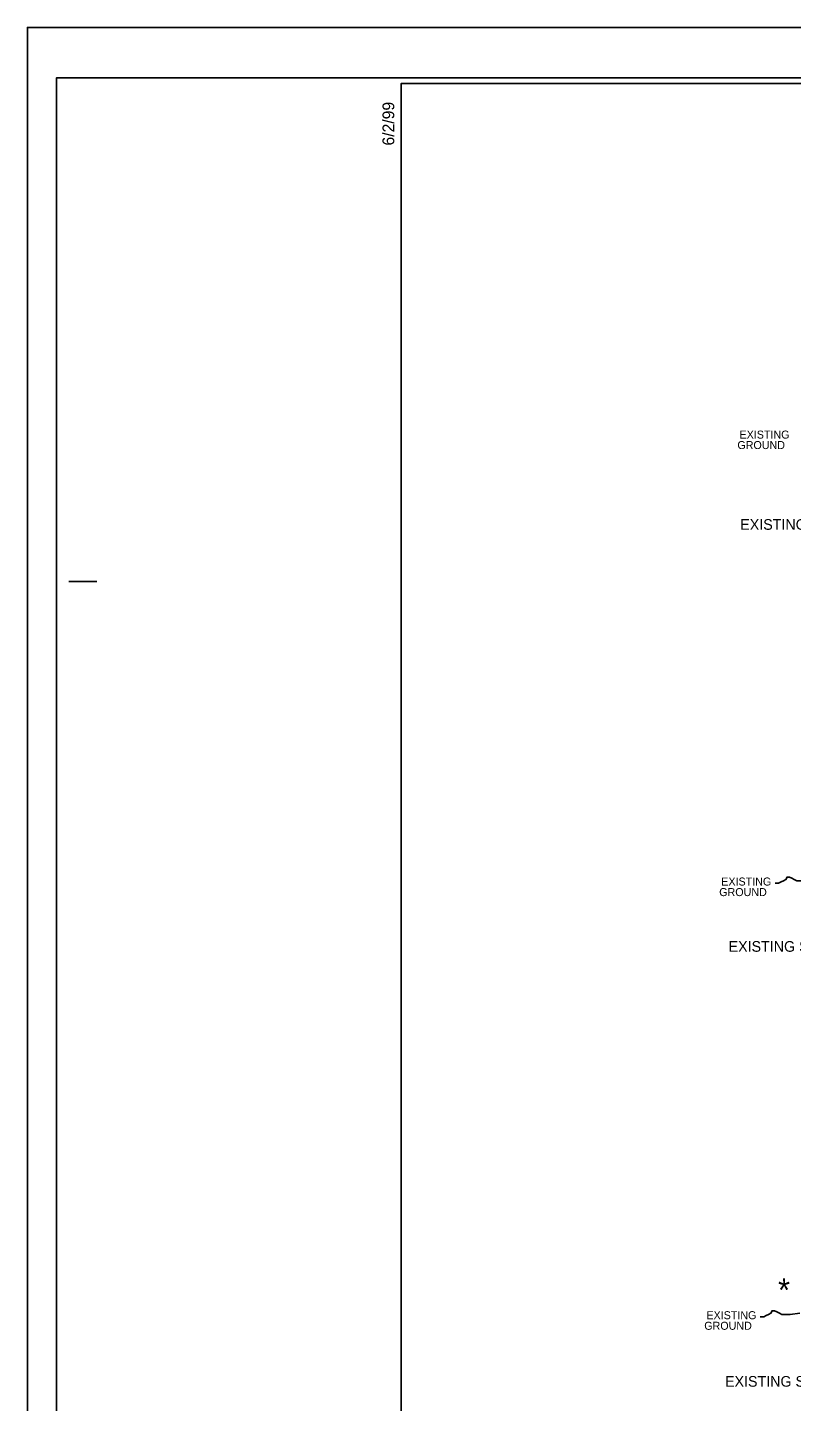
# Model space of a CAD drawing. Extents: x 1022283 to 1026986, y 174822 to 180471.
# Drawn here: x 1022283 to 1023136, y 178936 to 180471 of the extents above; entities that cross this region are included whole.
import ezdxf

# ---------------------------------------------------------------- set-up
doc = ezdxf.new("R2010")
doc.units = 0
for name, color, linetype in [('Sheet Cutting Line CELL', 7, 'Continuous'), ('Sheet Plot Border Inside CELL', 7, 'Continuous'), ('Sheet Plot Border Outside CELL', 7, 'Continuous'), ('Sheet Typical CELL', 7, 'Continuous'), ('Typical Slope Point Local CELL', 7, 'Continuous'), ('Typical Text General CELL', 7, 'Continuous')]:
    doc.layers.add(name, color=color, linetype=linetype)

msp = doc.modelspace()

# ---------------------------------------------------------------- linework, layer by layer
at = {"layer": 'Sheet Cutting Line CELL'}
for p, q in [((1026493.2, 180471.5), (1022283.2, 180471.5)), ((1022283.2, 180471.5), (1022283.2, 177721.5))]:
    msp.add_line(p, q, dxfattribs=at)
at = {"layer": 'Sheet Plot Border Inside CELL'}
msp.add_lwpolyline([(1026482, 180415.4), (1022315.7, 180415.4), (1022315.7, 177777.6), (1026482, 177777.6)], close=True, dxfattribs=at)
at = {"layer": 'Sheet Plot Border Outside CELL'}
msp.add_lwpolyline([(1026493.2, 180471.5), (1022283.2, 180471.5), (1022283.2, 177721.5), (1026493.2, 177721.5)], close=True, dxfattribs=at)
at = {"layer": 'Sheet Typical CELL'}
msp.add_line((1022329.5, 179852.7), (1022360.7, 179852.7), dxfattribs=at)
msp.add_lwpolyline([(1026450.7, 180409), (1022700.7, 180409), (1022700.7, 177784), (1026450.7, 177784)], close=True, dxfattribs=at)
at = {"layer": 'Typical Slope Point Local CELL'}
for points in [[(1023162.4, 179519.6), (1023151.6, 179518.3), (1023149, 179518.3), (1023144.9, 179518.3), (1023142.2, 179518.3), (1023139.5, 179519.6), (1023136.8, 179521), (1023134.1, 179522.3), (1023131.4, 179522.3), (1023130.1, 179519.6), (1023127.4, 179518.3), (1023124.7, 179516.9), (1023122, 179515.6), (1023119.3, 179515.6), (1023118.3, 179515.6)], [(1023162.4, 179519.6), (1023151.6, 179518.3), (1023149, 179518.3), (1023144.9, 179518.3), (1023142.2, 179518.3), (1023139.5, 179519.6), (1023136.8, 179521), (1023134.1, 179522.3), (1023131.4, 179522.3), (1023130.1, 179519.6), (1023127.4, 179518.3), (1023124.7, 179516.9), (1023122, 179515.6), (1023119.3, 179515.6), (1023118.3, 179515.6)], [(1023145.8, 179035.1), (1023135, 179033.8), (1023132.3, 179033.8), (1023128.2, 179033.8), (1023125.6, 179033.8), (1023122.9, 179035.1), (1023120.2, 179036.5), (1023117.5, 179037.8), (1023114.8, 179037.8), (1023113.4, 179035.1), (1023110.7, 179033.8), (1023108, 179032.4), (1023105.4, 179031.1), (1023102.7, 179031.1), (1023101.6, 179031.1)], [(1023145.8, 179035.1), (1023135, 179033.8), (1023132.3, 179033.8), (1023128.2, 179033.8), (1023125.6, 179033.8), (1023122.9, 179035.1), (1023120.2, 179036.5), (1023117.5, 179037.8), (1023114.8, 179037.8), (1023113.4, 179035.1), (1023110.7, 179033.8), (1023108, 179032.4), (1023105.4, 179031.1), (1023102.7, 179031.1), (1023101.6, 179031.1)]]:
    msp.add_lwpolyline(points, dxfattribs=at)

# ---------------------------------------------------------------- texts
at = {"layer": 'Sheet Typical CELL'}
msp.add_text('6/2/99', height=13.12, rotation=90, dxfattribs=at).set_placement((1022692.8, 180339.6))
at = {"layer": 'Typical Slope Point Local CELL'}
for s, height, p in [('EXISTING ', 8.94, (1023078.4, 180012.2)), ('EXISTING ', 8.94, (1023078.4, 180012.2)), ('GROUND', 8.94, (1023076, 180000.5)), ('GROUND', 8.94, (1023076, 180000.5)), ('EXISTING ', 8.94, (1023058, 179512.9)), ('EXISTING ', 8.94, (1023058, 179512.9)), ('GROUND', 8.94, (1023055.7, 179501.1)), ('GROUND', 8.94, (1023055.7, 179501.1)), ('*', 25.8, (1023121.4, 179048.2)), ('EXISTING ', 8.94, (1023041.4, 179028.4)), ('EXISTING ', 8.94, (1023041.4, 179028.4)), ('GROUND', 8.94, (1023039, 179016.6)), ('GROUND', 8.94, (1023039, 179016.6))]:
    msp.add_text(s, height=height, dxfattribs=at).set_placement(p)
at = {"layer": 'Typical Text General CELL'}
for p in [(1023079.2, 179910.3), (1023066.2, 179438.9), (1023062.2, 178953)]:
    msp.add_text('EXISTING SIDEWALK', height=11.898, dxfattribs=at).set_placement(p)

doc.saveas('drawing.dxf')
